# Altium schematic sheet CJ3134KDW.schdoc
size 127 x 101 mm
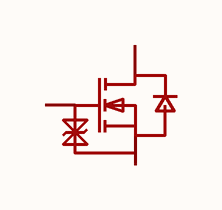
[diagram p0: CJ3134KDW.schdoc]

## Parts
Q?  cj3134kdw  [SOT-363_L2.0-W1.3-P0.65-LS2.1-BL]  (value not drawn)  (part A of 2)

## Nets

Not connected (* = marked no-connect by the designer): Q? 1(S1) 2(G1) 6(D1)

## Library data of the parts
Q? = cj3134kdw: 数量:2个N沟道;漏源电压(Vdss):20V;连续漏极电流(Id):750mA;导通电阻(RDS(on)):800mΩ@1.8V;耗散功率(Pd):150mW;阈值电压(Vgs(th)):1.1V;; Manufacturer: CJ(江苏长电/长晶); AddInBom: yes; ModelId: ea15c7b026c54341854a7f0d9614aed9; ModelName: SOT-363-6P_L2.0-W1.3-H1.1-LS2.0-P0.65; ModelTransform: 83.17133,78.74,0,90,0,0,0,0,0; Number: 2个N沟道; Drain to Source Voltage: 20V; Current - Continuous Drain(Id): 750mA; Pd - Power Dissipation: 150mW; Gate Threshold Voltage (Vgs(th)): 1.1V; Gate Charge(Qg): 750pC@4.5V; Input Capacitance(Ciss): 120pF; Reverse Transfer Capacitance (Crss@Vds): 15pF; Type: N沟道; Output Capacitance(Coss): 13pF; Vgs: ±12V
